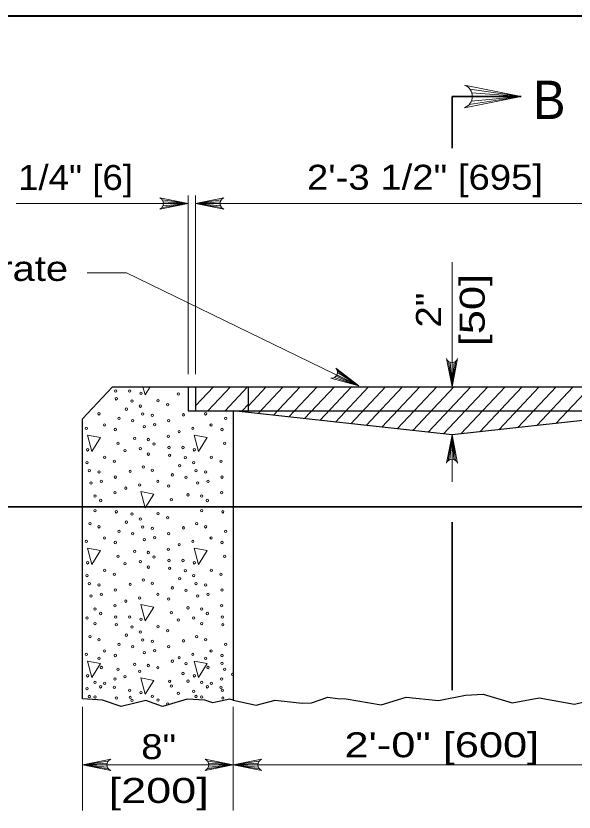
# Model space of a CAD drawing. Extents: x -410.5 to -376.5, y 1617.6 to 1661.6.
# Drawn here: x -405.776 to -402.283, y 1634.082 to 1639.062 of the extents above; entities that cross this region are included whole.
import ezdxf
from ezdxf.enums import TextEntityAlignment as Align

# ---------------------------------------------------------------- set-up
doc = ezdxf.new("R2010")
doc.units = 0
doc.header["$LTSCALE"] = 0.062
doc.layers.add('1', color=7, linetype='Continuous', lineweight=13)

msp = doc.modelspace()

# ---------------------------------------------------------------- linework, layer by layer
at = {"layer": '1', "lineweight": 25}
for p, q in [((-408.45475, 1639.06183), (-376.95475, 1639.06183)), ((-404.69908, 1636.74175), (-404.3215, 1636.74175)), ((-404.65192, 1636.74175), (-404.65192, 1636.59183)), ((-404.3215, 1636.59183), (-401.77275, 1636.59183))]:
    msp.add_line(p, q, dxfattribs=at)
at = {"layer": '1'}
for p, q in [((-402.93492, 1638.603), (-402.61442, 1638.55817)), ((-402.92408, 1638.58083), (-402.61442, 1638.55817)), ((-402.93875, 1638.50858), (-402.61442, 1638.55817)), ((-402.92642, 1638.52933), (-402.61442, 1638.55817)), ((-402.92075, 1638.55817), (-402.61442, 1638.55817)), ((-404.69908, 1636.82042), (-404.69908, 1637.93875)), ((-404.65192, 1636.82042), (-404.65192, 1637.93875)), ((-405.77508, 1637.88875), (-404.69908, 1637.88875)), ((-404.86125, 1637.864), (-404.69908, 1637.88875)), ((-404.85933, 1637.91117), (-404.69908, 1637.88875)), ((-404.85508, 1637.87442), (-404.69908, 1637.88875)), ((-404.85392, 1637.90008), (-404.69908, 1637.88875)), ((-404.85225, 1637.88875), (-404.69908, 1637.88875)), ((-404.49167, 1637.91117), (-404.65192, 1637.88875)), ((-404.49708, 1637.90008), (-404.65192, 1637.88875)), ((-404.49875, 1637.88875), (-404.65192, 1637.88875)), ((-404.49592, 1637.87442), (-404.65192, 1637.88875)), ((-404.48975, 1637.864), (-404.65192, 1637.88875)), ((-403.04708, 1637.52075), (-403.04708, 1636.74175)), ((-403.0695, 1636.902), (-403.04708, 1636.74175)), ((-403.05842, 1636.8965), (-403.04708, 1636.74175)), ((-403.02233, 1636.90383), (-403.04708, 1636.74175)), ((-403.03275, 1636.89775), (-403.04708, 1636.74175)), ((-403.04708, 1636.89492), (-403.04708, 1636.74175)), ((-403.04708, 1636.74175), (-403.04708, 1636.89167)), ((-403.76517, 1636.84342), (-403.63083, 1636.74933)), ((-403.76425, 1636.83133), (-403.63083, 1636.74933)), ((-403.78442, 1636.80025), (-403.63083, 1636.74933)), ((-403.77467, 1636.80775), (-403.63083, 1636.74933)), ((-403.76808, 1636.81717), (-403.63083, 1636.74933)), ((-404.69908, 1636.74175), (-404.69908, 1636.59183)), ((-404.65192, 1636.62275), (-404.53967, 1636.74167)), ((-404.65192, 1636.73592), (-404.6465, 1636.74167)), ((-404.57433, 1636.59192), (-404.43292, 1636.74167)), ((-404.46758, 1636.59192), (-404.32608, 1636.74167)), ((-404.3215, 1636.62417), (-404.21042, 1636.74175)), ((-404.3215, 1636.73733), (-404.31725, 1636.74175)), ((-404.26125, 1636.57492), (-404.10367, 1636.74175)), ((-404.1645, 1636.56433), (-403.99683, 1636.74175)), ((-404.06767, 1636.55375), (-403.89, 1636.74175)), ((-403.97092, 1636.54308), (-403.78325, 1636.74175)), ((-403.87417, 1636.5325), (-403.67633, 1636.74183)), ((-403.77733, 1636.52192), (-403.56967, 1636.74175)), ((-403.6805, 1636.51125), (-403.46283, 1636.74175)), ((-403.58367, 1636.50067), (-403.356, 1636.74175)), ((-403.48692, 1636.49008), (-403.24925, 1636.74175)), ((-403.39017, 1636.4795), (-403.14242, 1636.74175)), ((-403.29333, 1636.46892), (-403.03567, 1636.74175)), ((-403.19658, 1636.45833), (-402.92892, 1636.74175)), ((-403.09983, 1636.44775), (-402.82208, 1636.74175)), ((-402.99292, 1636.44783), (-402.71525, 1636.74175)), ((-402.87383, 1636.46083), (-402.6085, 1636.74175)), ((-402.75467, 1636.47383), (-402.50167, 1636.74175)), ((-402.6355, 1636.48692), (-402.39483, 1636.74175)), ((-402.51633, 1636.5), (-402.28808, 1636.74175)), ((-402.39733, 1636.513), (-402.18125, 1636.74175)), ((-404.36075, 1636.59192), (-404.3215, 1636.63342)), ((-404.4065, 1636.59083), (-404.4055, 1636.59183)), ((-404.358, 1636.5855), (-404.35208, 1636.59183)), ((-405.24658, 1636.42425), (-405.32842, 1636.44017)), ((-403.07192, 1636.27975), (-403.04708, 1636.44192)), ((-403.0615, 1636.28592), (-403.04708, 1636.44192)), ((-403.04708, 1636.28875), (-403.04708, 1636.44192)), ((-403.03575, 1636.28708), (-403.04708, 1636.44192)), ((-403.02467, 1636.28167), (-403.04708, 1636.44192)), ((-403.04708, 1636.44192), (-403.04708, 1636.14758)), ((-405.32842, 1635.7335), (-405.3015, 1635.631)), ((-405.32842, 1635.02675), (-405.3015, 1634.92433)), ((-405.35992, 1634.09325), (-405.35992, 1634.74117)), ((-404.41592, 1634.09325), (-404.41592, 1634.74117)), ((-405.19967, 1634.40017), (-405.35992, 1634.37775)), ((-405.20508, 1634.38908), (-405.35992, 1634.37775)), ((-404.57617, 1634.40017), (-404.41592, 1634.37775)), ((-404.57075, 1634.38908), (-404.41592, 1634.37775)), ((-404.25567, 1634.40017), (-404.41592, 1634.37775)), ((-404.26108, 1634.38908), (-404.41592, 1634.37775)), ((-405.35992, 1634.37775), (-404.67917, 1634.37775)), ((-405.20675, 1634.37775), (-405.35992, 1634.37775)), ((-405.20392, 1634.36333), (-405.35992, 1634.37775)), ((-405.19775, 1634.353), (-405.35992, 1634.37775)), ((-404.7525, 1634.37775), (-404.41592, 1634.37775)), ((-404.57808, 1634.353), (-404.41592, 1634.37775)), ((-404.57192, 1634.36333), (-404.41592, 1634.37775)), ((-404.56908, 1634.37775), (-404.41592, 1634.37775)), ((-404.41592, 1634.37775), (-402.5025, 1634.37775)), ((-404.26275, 1634.37775), (-404.41592, 1634.37775)), ((-404.25992, 1634.36333), (-404.41592, 1634.37775)), ((-404.25375, 1634.353), (-404.41592, 1634.37775)), ((-402.5235, 1634.37775), (-401.67833, 1634.37775))]:
    msp.add_line(p, q, dxfattribs=at)
at = {"layer": '1', "lineweight": 35}
for p, q in [((-403.04708, 1638.55817), (-402.61442, 1638.55817)), ((-403.04708, 1638.23483), (-403.04708, 1638.55817)), ((-405.888, 1635.99217), (-400.21625, 1635.99217)), ((-403.04708, 1634.84533), (-403.04708, 1635.89658))]:
    msp.add_line(p, q, dxfattribs=at)
at = {"layer": '1', "lineweight": 40}
msp.add_lwpolyline([(-408.45475, 1639.06183), (-376.95475, 1639.06183), (-376.95475, 1618.06183), (-408.45475, 1618.06183)], close=True, dxfattribs=at)
msp.add_lwpolyline([(-408.45475, 1639.06183), (-376.95475, 1639.06183), (-376.95475, 1618.06183), (-408.45475, 1618.06183)], close=True, dxfattribs=at)
at = {"layer": '1'}
for points in [[(-402.96842, 1638.48733), (-402.61442, 1638.55817), (-402.96842, 1638.62892)], [(-404.87608, 1637.85342), (-404.69908, 1637.88875), (-404.87608, 1637.92417)], [(-404.47492, 1637.85342), (-404.65192, 1637.88875), (-404.47492, 1637.92417)], [(-404.65192, 1637.88875), (-402.994, 1637.88875), (-401.86958, 1637.88875), (-401.44233, 1637.88875)], [(-403.63083, 1636.74933), (-405.084, 1637.45483), (-405.33, 1637.45483)], [(-403.01175, 1636.91875), (-403.04708, 1636.74175), (-403.0825, 1636.91875)], [(-403.77375, 1636.8595), (-403.63083, 1636.74933), (-403.80517, 1636.796)], [(-404.98108, 1636.74167), (-404.96775, 1636.69108), (-404.93558, 1636.74167)], [(-405.32842, 1636.44017), (-405.3015, 1636.33775), (-405.24658, 1636.42425)], [(-403.0825, 1636.26492), (-403.04708, 1636.44192), (-403.01175, 1636.26492)], [(-405.3015, 1635.631), (-405.24658, 1635.7175), (-405.32842, 1635.7335)], [(-405.3015, 1634.92433), (-405.24658, 1635.01083), (-405.32842, 1635.02675)], [(-405.18292, 1634.34233), (-405.35992, 1634.37775), (-405.18292, 1634.41317)], [(-404.59292, 1634.34233), (-404.41592, 1634.37775), (-404.59292, 1634.41317)], [(-404.23892, 1634.34233), (-404.41592, 1634.37775), (-404.23892, 1634.41317)]]:
    msp.add_lwpolyline(points, dxfattribs=at)
at = {"layer": '1', "lineweight": 25}
for points in [[(-404.41592, 1634.78325), (-404.43733, 1634.78808), (-404.54342, 1634.76608), (-404.59358, 1634.78242), (-404.7045, 1634.78875), (-404.85808, 1634.74258), (-404.96408, 1634.78033), (-405.11767, 1634.74325), (-405.23408, 1634.78308), (-405.35992, 1634.79117), (-405.35992, 1636.54183), (-405.17108, 1636.74175), (-404.69908, 1636.74175)], [(-404.69908, 1636.74175), (-404.69908, 1636.59183), (-404.41592, 1636.59183), (-404.41592, 1634.78325)], [(-404.41592, 1634.78325), (-404.2725, 1634.75117), (-404.153, 1634.78225), (-403.98442, 1634.76358), (-403.92575, 1634.76642), (-403.82517, 1634.80067), (-403.76458, 1634.79342), (-403.7105, 1634.79125), (-403.49083, 1634.75217), (-403.33433, 1634.80033), (-403.13075, 1634.77958), (-402.962, 1634.81358), (-402.852, 1634.82042), (-402.67125, 1634.76517), (-402.5025, 1634.79617), (-402.27992, 1634.75808), (-402.12158, 1634.79417), (-402.07225, 1634.80517), (-401.81283, 1634.767), (-401.67833, 1634.79958)]]:
    msp.add_lwpolyline(points, dxfattribs=at)
msp.add_lwpolyline([(-403.04708, 1636.44192), (-404.41592, 1636.59183), (-404.3215, 1636.59183), (-404.3215, 1636.74175), (-401.77275, 1636.74175), (-401.77275, 1636.59183), (-401.67833, 1636.59183)], close=True, dxfattribs=at)
at = {"layer": '1'}
for points in [[(-404.661, 1636.44017), (-404.634, 1636.33775), (-404.579, 1636.42425)], [(-404.99475, 1636.08683), (-404.96775, 1635.98442), (-404.91275, 1636.07083)], [(-404.661, 1635.7335), (-404.634, 1635.631), (-404.579, 1635.7175)], [(-404.99475, 1635.38008), (-404.96775, 1635.27775), (-404.91275, 1635.36417)], [(-404.661, 1635.02675), (-404.634, 1634.92433), (-404.579, 1635.01083)], [(-404.99475, 1634.92158), (-404.96775, 1634.81917), (-404.91275, 1634.90558)]]:
    msp.add_lwpolyline(points, close=True, dxfattribs=at)
for centre, radius, start, end in [((-402.99703, 1638.55823), 0.0764, 292.08605, 67.91218), ((-404.89041, 1637.88882), 0.0382, 292.08605, 67.91218), ((-404.46062, 1637.88882), 0.0382, 112.08782, 247.91395), ((-403.04715, 1636.93301), 0.0382, 202.08782, 337.91395), ((-403.8023, 1636.83406), 0.0382, 265.7726, 41.59873), ((-403.04707, 1636.2506), 0.0382, 22.08782, 157.91395), ((-405.16862, 1634.3778), 0.0382, 112.08782, 247.91395), ((-404.60721, 1634.3778), 0.0382, 292.08605, 67.91218), ((-404.22462, 1634.3778), 0.0382, 112.08782, 247.91395)]:
    msp.add_arc(centre, radius, start, end, dxfattribs=at)
for centre, major_axis in [((-405.15147, 1636.71583), (0, -0.00756)), ((-405.06491, 1636.71583), (0, 0.00756)), ((-404.99377, 1636.70152), (0, -0.00756)), ((-404.76031, 1636.69675), (0, 0.00756)), ((-405.1488, 1636.66719), (0, -0.00756)), ((-405.0505, 1636.65288), (0, 0.00756)), ((-404.99738, 1636.62137), (0, 0.00756)), ((-404.88652, 1636.65476), (0, -0.00756)), ((-404.82706, 1636.62997), (0, -0.00756)), ((-405.25721, 1636.57337), (0, -0.00756)), ((-405.08572, 1636.60229), (0, 0.00756)), ((-404.98292, 1636.57178), (0, 0.00756)), ((-404.5897, 1636.57337), (0, -0.00756)), ((-405.13105, 1636.54475), (0, 0.00756)), ((-405.04605, 1636.52979), (0, 0.00756)), ((-404.92257, 1636.56313), (0, -0.00756)), ((-404.81983, 1636.53068), (0, -0.00756)), ((-404.7276, 1636.56672), (0, -0.00756)), ((-404.46354, 1636.54475), (0, 0.00756)), ((-405.33653, 1636.48174), (0, -0.00756)), ((-405.22211, 1636.5037), (0, 0.00756)), ((-405.15358, 1636.47508), (0, 0.00756)), ((-404.97218, 1636.49352), (0, 0.00756)), ((-404.90727, 1636.505), (0, -0.00756)), ((-404.66902, 1636.48174), (0, -0.00756)), ((-404.5546, 1636.5037), (0, 0.00756)), ((-404.48607, 1636.47508), (0, 0.00756)), ((-404.82311, 1636.43309), (0, -0.00756)), ((-404.75469, 1636.46171), (0, -0.00756)), ((-405.13734, 1636.38922), (0, 0.00756)), ((-405.03282, 1636.41978), (0, 0.00756)), ((-404.94776, 1636.41242), (0, 0.00756)), ((-404.91233, 1636.38445), (0, -0.00756)), ((-404.46983, 1636.38922), (0, 0.00756)), ((-405.32752, 1636.34817), (0, -0.00756)), ((-405.09406, 1636.3434), (0, 0.00756)), ((-404.99766, 1636.35583), (0, 0.00756)), ((-404.81771, 1636.36248), (0, -0.00756)), ((-404.73116, 1636.36248), (0, 0.00756)), ((-404.66001, 1636.34817), (0, -0.00756)), ((-405.22027, 1636.30141), (0, -0.00756)), ((-405.16081, 1636.27662), (0, -0.00756)), ((-404.94687, 1636.32114), (0, -0.00756)), ((-404.81504, 1636.31384), (0, -0.00756)), ((-404.71675, 1636.29953), (0, 0.00756)), ((-404.55277, 1636.30141), (0, -0.00756)), ((-404.4933, 1636.27662), (0, -0.00756)), ((-405.33114, 1636.26802), (0, 0.00756)), ((-404.97841, 1636.24005), (0, -0.00756)), ((-404.75196, 1636.24894), (0, 0.00756)), ((-404.66363, 1636.26802), (0, 0.00756)), ((-405.31667, 1636.21843), (0, 0.00756)), ((-405.25632, 1636.20978), (0, -0.00756)), ((-405.15358, 1636.17733), (0, -0.00756)), ((-405.06135, 1636.21337), (0, -0.00756)), ((-404.92346, 1636.22002), (0, -0.00756)), ((-404.7973, 1636.1914), (0, 0.00756)), ((-404.7123, 1636.17644), (0, 0.00756)), ((-404.64917, 1636.21843), (0, 0.00756)), ((-404.58881, 1636.20978), (0, -0.00756)), ((-404.48607, 1636.17733), (0, -0.00756)), ((-405.30594, 1636.14017), (0, 0.00756)), ((-405.24102, 1636.15165), (0, -0.00756)), ((-405.00278, 1636.12839), (0, -0.00756)), ((-404.88836, 1636.15035), (0, 0.00756)), ((-404.63843, 1636.14017), (0, 0.00756)), ((-404.57351, 1636.15165), (0, -0.00756)), ((-405.15686, 1636.07974), (0, -0.00756)), ((-405.08844, 1636.10836), (0, -0.00756)), ((-404.81983, 1636.12173), (0, 0.00756)), ((-404.48935, 1636.07974), (0, -0.00756)), ((-405.28152, 1636.05907), (0, 0.00756)), ((-405.24608, 1636.0311), (0, -0.00756)), ((-404.80358, 1636.03587), (0, 0.00756)), ((-404.69906, 1636.06643), (0, 0.00756)), ((-404.61401, 1636.05907), (0, 0.00756)), ((-404.57858, 1636.0311), (0, -0.00756)), ((-405.28063, 1635.96779), (0, -0.00756)), ((-405.1488, 1635.96049), (0, -0.00756)), ((-405.0505, 1635.94618), (0, 0.00756)), ((-404.88652, 1635.94806), (0, -0.00756)), ((-404.61312, 1635.96779), (0, -0.00756)), ((-404.48129, 1635.96049), (0, -0.00756)), ((-405.31217, 1635.8867), (0, -0.00756)), ((-405.08572, 1635.89559), (0, 0.00756)), ((-404.99738, 1635.91467), (0, 0.00756)), ((-404.82706, 1635.92327), (0, -0.00756)), ((-404.64466, 1635.8867), (0, -0.00756)), ((-405.25721, 1635.86667), (0, -0.00756)), ((-405.13105, 1635.83805), (0, 0.00756)), ((-404.98292, 1635.86508), (0, 0.00756)), ((-404.92257, 1635.85643), (0, -0.00756)), ((-404.7276, 1635.86002), (0, -0.00756)), ((-404.5897, 1635.86667), (0, -0.00756)), ((-404.46354, 1635.83805), (0, 0.00756)), ((-405.33653, 1635.77504), (0, -0.00756)), ((-405.22211, 1635.797), (0, 0.00756)), ((-405.04605, 1635.82309), (0, 0.00756)), ((-404.97218, 1635.78682), (0, 0.00756)), ((-404.90727, 1635.7983), (0, -0.00756)), ((-404.81983, 1635.82398), (0, -0.00756)), ((-404.66902, 1635.77504), (0, -0.00756)), ((-404.5546, 1635.797), (0, 0.00756)), ((-405.15358, 1635.76838), (0, 0.00756)), ((-404.82311, 1635.72639), (0, -0.00756)), ((-404.75469, 1635.75501), (0, -0.00756)), ((-404.48607, 1635.76838), (0, 0.00756)), ((-405.13734, 1635.68252), (0, 0.00756)), ((-405.03282, 1635.71308), (0, 0.00756)), ((-404.94776, 1635.70572), (0, 0.00756)), ((-404.91233, 1635.67775), (0, -0.00756)), ((-404.46983, 1635.68252), (0, 0.00756)), ((-405.32752, 1635.64147), (0, -0.00756)), ((-405.09406, 1635.6367), (0, 0.00756)), ((-404.99766, 1635.64913), (0, 0.00756)), ((-404.81771, 1635.65578), (0, -0.00756)), ((-404.73116, 1635.65578), (0, 0.00756)), ((-404.66001, 1635.64147), (0, -0.00756)), ((-405.22027, 1635.59471), (0, -0.00756)), ((-404.94687, 1635.61444), (0, -0.00756)), ((-404.81504, 1635.60714), (0, -0.00756)), ((-404.71675, 1635.59283), (0, 0.00756)), ((-404.55277, 1635.59471), (0, -0.00756)), ((-405.33114, 1635.56132), (0, 0.00756)), ((-405.16081, 1635.56992), (0, -0.00756)), ((-404.97841, 1635.53335), (0, -0.00756)), ((-404.75196, 1635.54224), (0, 0.00756)), ((-404.66363, 1635.56132), (0, 0.00756)), ((-404.4933, 1635.56992), (0, -0.00756)), ((-405.31667, 1635.51173), (0, 0.00756)), ((-405.25632, 1635.50308), (0, -0.00756)), ((-405.06135, 1635.50667), (0, -0.00756)), ((-404.92346, 1635.51332), (0, -0.00756)), ((-404.7973, 1635.4847), (0, 0.00756)), ((-404.64917, 1635.51173), (0, 0.00756)), ((-404.58881, 1635.50308), (0, -0.00756)), ((-405.30594, 1635.43347), (0, 0.00756)), ((-405.24102, 1635.44495), (0, -0.00756)), ((-405.15358, 1635.47063), (0, -0.00756)), ((-404.88836, 1635.44365), (0, 0.00756)), ((-404.7123, 1635.46974), (0, 0.00756)), ((-404.63843, 1635.43347), (0, 0.00756)), ((-404.57351, 1635.44495), (0, -0.00756)), ((-404.48607, 1635.47063), (0, -0.00756)), ((-405.08844, 1635.40166), (0, -0.00756)), ((-405.00278, 1635.42169), (0, -0.00756)), ((-404.81983, 1635.41503), (0, 0.00756)), ((-405.28152, 1635.35237), (0, 0.00756)), ((-405.15686, 1635.37304), (0, -0.00756)), ((-404.80358, 1635.32917), (0, 0.00756)), ((-404.69906, 1635.35973), (0, 0.00756)), ((-404.61401, 1635.35237), (0, 0.00756)), ((-404.48935, 1635.37304), (0, -0.00756)), ((-405.33141, 1635.29578), (0, 0.00756)), ((-405.24608, 1635.3244), (0, -0.00756)), ((-405.15147, 1635.30243), (0, -0.00756)), ((-405.06491, 1635.30243), (0, 0.00756)), ((-404.99377, 1635.28812), (0, -0.00756)), ((-404.76031, 1635.28335), (0, 0.00756)), ((-404.66391, 1635.29578), (0, 0.00756)), ((-404.57858, 1635.3244), (0, -0.00756)), ((-404.48396, 1635.30243), (0, -0.00756)), ((-405.28063, 1635.26109), (0, -0.00756)), ((-405.1488, 1635.25379), (0, -0.00756)), ((-405.0505, 1635.23948), (0, 0.00756)), ((-404.88652, 1635.24136), (0, -0.00756)), ((-404.61312, 1635.26109), (0, -0.00756)), ((-404.48129, 1635.25379), (0, -0.00756)), ((-405.31217, 1635.18), (0, -0.00756)), ((-405.08572, 1635.18889), (0, 0.00756)), ((-404.99738, 1635.20797), (0, 0.00756)), ((-404.82706, 1635.21657), (0, -0.00756)), ((-404.64466, 1635.18), (0, -0.00756)), ((-405.25721, 1635.15997), (0, -0.00756)), ((-405.13105, 1635.13135), (0, 0.00756)), ((-404.98292, 1635.15838), (0, 0.00756)), ((-404.92257, 1635.14973), (0, -0.00756)), ((-404.7276, 1635.15332), (0, -0.00756)), ((-404.5897, 1635.15997), (0, -0.00756)), ((-404.46354, 1635.13135), (0, 0.00756)), ((-405.22211, 1635.0903), (0, 0.00756)), ((-405.04605, 1635.11639), (0, 0.00756)), ((-404.97218, 1635.08012), (0, 0.00756)), ((-404.90727, 1635.0916), (0, -0.00756)), ((-404.81983, 1635.11728), (0, -0.00756)), ((-404.5546, 1635.0903), (0, 0.00756)), ((-405.33653, 1635.06834), (0, -0.00756)), ((-405.25632, 1635.04456), (0, -0.00756)), ((-405.15358, 1635.06168), (0, 0.00756)), ((-404.75469, 1635.04831), (0, -0.00756)), ((-404.66902, 1635.06834), (0, -0.00756)), ((-404.58881, 1635.04456), (0, -0.00756)), ((-404.48607, 1635.06168), (0, 0.00756)), ((-405.24102, 1634.98644), (0, -0.00756)), ((-405.03282, 1635.00638), (0, 0.00756)), ((-404.94776, 1634.99902), (0, 0.00756)), ((-404.88836, 1634.98514), (0, 0.00756)), ((-404.7973, 1635.02619), (0, 0.00756)), ((-404.7123, 1635.01123), (0, 0.00756)), ((-404.57351, 1634.98644), (0, -0.00756)), ((-404.48607, 1635.01211), (0, -0.00756)), ((-405.32752, 1634.93477), (0, -0.00756)), ((-405.13734, 1634.97582), (0, 0.00756)), ((-405.09406, 1634.93), (0, 0.00756)), ((-405.00278, 1634.96317), (0, -0.00756)), ((-404.73116, 1634.94908), (0, 0.00756)), ((-404.66001, 1634.93477), (0, -0.00756)), ((-404.46983, 1634.97582), (0, 0.00756)), ((-404.42093, 1634.94315), (0, -0.00756)), ((-405.28152, 1634.89386), (0, 0.00756)), ((-405.22027, 1634.88801), (0, -0.00756)), ((-405.15686, 1634.91453), (0, -0.00756)), ((-404.81504, 1634.90044), (0, -0.00756)), ((-404.69906, 1634.90122), (0, 0.00756)), ((-404.61401, 1634.89386), (0, 0.00756)), ((-404.55277, 1634.88801), (0, -0.00756)), ((-404.48935, 1634.91453), (0, -0.00756)), ((-405.33114, 1634.85462), (0, 0.00756)), ((-405.24609, 1634.86588), (0, -0.00756)), ((-405.16081, 1634.86322), (0, -0.00756)), ((-405.06491, 1634.84392), (0, 0.00756)), ((-404.99377, 1634.82961), (0, -0.00756)), ((-404.80358, 1634.87065), (0, 0.00756)), ((-404.66391, 1634.83726), (0, 0.00756)), ((-404.57858, 1634.86588), (0, -0.00756)), ((-404.4933, 1634.86322), (0, -0.00756)), ((-404.48396, 1634.84392), (0, -0.00756)), ((-405.31667, 1634.80503), (0, 0.00756)), ((-405.28063, 1634.80258), (0, -0.00756)), ((-405.1488, 1634.79527), (0, -0.00756)), ((-405.06135, 1634.79997), (0, -0.00756)), ((-405.05051, 1634.78096), (0, 0.00756)), ((-404.92346, 1634.80662), (0, -0.00756)), ((-404.88652, 1634.78285), (0, -0.00756)), ((-404.76031, 1634.82484), (0, 0.00756)), ((-404.64917, 1634.80503), (0, 0.00756)), ((-404.61312, 1634.80258), (0, -0.00756)), ((-404.48129, 1634.79527), (0, -0.00756)), ((-404.82706, 1634.75805), (0, -0.00756))]:
    msp.add_ellipse(centre, major_axis=major_axis, ratio=0.944543, dxfattribs=at)

# ---------------------------------------------------------------- texts
for s, height, width, p in [('B', 0.24, 0.95, (-402.4385, 1638.417)), ('8"', 0.156, 1.15, (-404.88292, 1634.41342)), ('[200]', 0.156, 1.35, (-404.88292, 1634.13942))]:
    msp.add_text(s, height=height, dxfattribs=dict(at, width=width)).set_placement(p, align=Align.CENTER)
for s, width, p in [('1/4" [6]', 1.1, (-405.763, 1637.97342)), ('2\'-3 1/2" [695]', 1.15, (-403.95517, 1637.97483)), ('Grate', 1.2, (-406.0755, 1637.40442)), ('2\'-0" [600]', 1.3, (-403.72017, 1634.42525))]:
    msp.add_text(s, height=0.156, dxfattribs=dict(at, width=width)).set_placement(p)
for s, width, p in [('[50]', 1.3, (-402.84267, 1637.22221)), ('2"', 1.15, (-403.11667, 1637.22221))]:
    msp.add_text(s, height=0.156, rotation=90, dxfattribs=dict(at, width=width)).set_placement(p, align=Align.CENTER)

doc.saveas('drawing.dxf')
